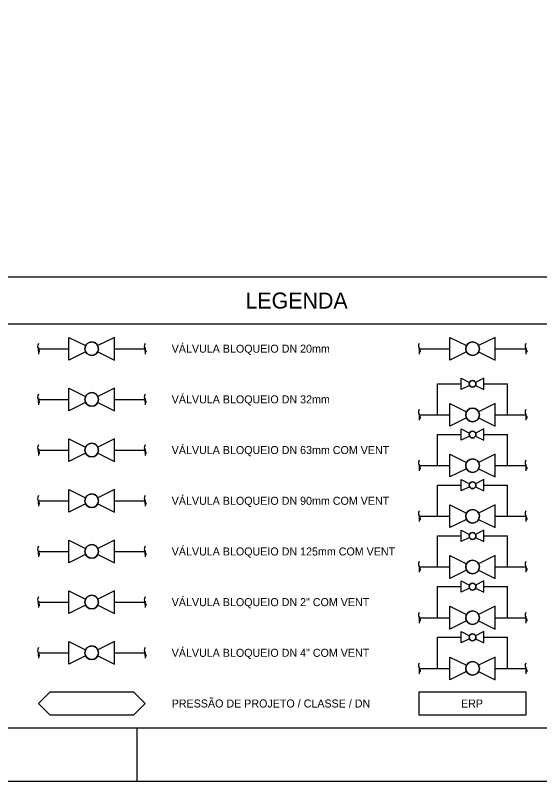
# Model space of a CAD drawing. Extents: x -1349 to -508, y 286 to 880.
# Drawn here: x -1031.4 to -933.1, y 285.8 to 429.5 of the extents above; entities that cross this region are included whole.
import ezdxf

# ---------------------------------------------------------------- set-up
doc = ezdxf.new("R2010")
doc.units = 0
for name, color, linetype in [('FORMATO', 7, 'Continuous'), ('LEGENDA', 7, 'Continuous'), ('VALVULA_ACO_10', 7, 'Continuous'), ('VALVULA_ACO_12', 7, 'Continuous'), ('VALVULA_ACO_14', 7, 'Continuous'), ('VALVULA_ACO_16', 7, 'Continuous'), ('VALVULA_ACO_18', 7, 'Continuous'), ('VALVULA_ACO_2', 7, 'Continuous'), ('VALVULA_ACO_4', 7, 'Continuous'), ('VALVULA_ACO_6', 7, 'Continuous'), ('VALVULA_ACO_8', 7, 'Continuous'), ('VALVULA_PEAD_125', 7, 'Continuous'), ('VALVULA_PEAD_20', 7, 'Continuous'), ('VALVULA_PEAD_32', 7, 'Continuous'), ('VALVULA_PEAD_63', 7, 'Continuous'), ('VALVULA_PEAD_90', 7, 'Continuous')]:
    doc.layers.add(name, color=color, linetype=linetype)

msp = doc.modelspace()

# ---------------------------------------------------------------- linework, layer by layer
at = {"layer": 'FORMATO'}
msp.add_line((-518.04, 295.82), (-1344.05, 295.82), dxfattribs=at)
msp.add_lwpolyline([(-1349.05, 879.82), (-508.05, 879.82), (-508.05, 285.82), (-1349.05, 285.82)], close=True, dxfattribs=at)
for points in [[(-518.04, 380.36), (-1324.05, 380.36)], [(-1324.05, 371.63), (-693.05, 371.63)], [(-1008.55, 285.82), (-1008.55, 295.82)]]:
    msp.add_lwpolyline(points, dxfattribs=at)
at = {"layer": 'LEGENDA'}
for points in [[(-1024.9, 302.66), (-1009.27, 302.66), (-1007.08, 300.47), (-1007.08, 300.47), (-1009.27, 298.28), (-1024.9, 298.28), (-1027.08, 300.47), (-1027.08, 300.47)], [(-955.66, 302.66), (-935.66, 302.66), (-935.66, 298.28), (-955.66, 298.28)]]:
    msp.add_lwpolyline(points, close=True, dxfattribs=at)
at = {"layer": 'VALVULA_ACO_10'}
for points in [[(-952.23, 350.89), (-947.79, 350.89)], [(-952.23, 345.06), (-952.23, 350.89)], [(-946.23, 350.6), (-947.79, 349.82), (-947.79, 351.95), (-946.23, 351.17)], [(-945.09, 350.6), (-943.54, 349.82), (-943.54, 351.95), (-945.09, 351.17)], [(-943.54, 350.89), (-939.09, 350.89)], [(-939.09, 345.06), (-939.09, 350.89)], [(-946.8, 344.49), (-949.92, 342.94), (-949.92, 347.19), (-946.8, 345.63)], [(-944.52, 344.49), (-941.41, 342.94), (-941.41, 347.19), (-944.52, 345.63)], [(-955.66, 345.06), (-949.92, 345.06)], [(-941.41, 345.06), (-935.66, 345.06)]]:
    msp.add_lwpolyline(points, dxfattribs=at)
for centre, radius in [((-945.66, 350.89), 0.638), ((-945.66, 345.06), 1.28)]:
    msp.add_circle(centre, radius, dxfattribs=at)
for centre, radius, start, end in [((-945.66, 350.89), 0.638, 0, 180), ((-945.66, 350.89), 0.638, 180, 0), ((-945.66, 345.06), 1.28, 0, 180), ((-945.66, 345.06), 1.28, 180, 0)]:
    msp.add_arc(centre, radius, start, end, dxfattribs=at)
for points in [[(-955.66, 346.06), (-955.91, 345.56), (-955.66, 345.06), (-955.41, 344.56), (-955.66, 344.06), (-955.66, 346.06), (-955.66, 344.06)], [(-935.66, 346.06), (-935.91, 345.56), (-935.66, 345.06), (-935.41, 344.56), (-935.66, 344.06), (-935.66, 346.06), (-935.66, 344.06)]]:
    msp.add_open_spline(points, degree=3, dxfattribs=at)
at = {"layer": 'VALVULA_ACO_12'}
for points in [[(-946.23, 341.1), (-947.79, 340.32), (-947.79, 342.45), (-946.23, 341.67)], [(-945.09, 341.1), (-943.54, 340.32), (-943.54, 342.45), (-945.09, 341.67)], [(-952.23, 341.39), (-947.79, 341.39)], [(-952.23, 335.56), (-952.23, 341.39)], [(-943.54, 341.39), (-939.09, 341.39)], [(-939.09, 335.56), (-939.09, 341.39)], [(-946.8, 334.99), (-949.92, 333.44), (-949.92, 337.69), (-946.8, 336.13)], [(-944.52, 334.99), (-941.41, 333.44), (-941.41, 337.69), (-944.52, 336.13)], [(-955.66, 335.56), (-949.92, 335.56)], [(-941.41, 335.56), (-935.66, 335.56)]]:
    msp.add_lwpolyline(points, dxfattribs=at)
for centre, radius in [((-945.66, 341.39), 0.638), ((-945.66, 335.56), 1.28)]:
    msp.add_circle(centre, radius, dxfattribs=at)
for centre, radius, start, end in [((-945.66, 341.39), 0.638, 0, 180), ((-945.66, 341.39), 0.638, 180, 0), ((-945.66, 335.56), 1.28, 0, 180), ((-945.66, 335.56), 1.28, 180, 0)]:
    msp.add_arc(centre, radius, start, end, dxfattribs=at)
for points in [[(-955.66, 336.56), (-955.91, 336.06), (-955.66, 335.56), (-955.41, 335.06), (-955.66, 334.56), (-955.66, 336.56), (-955.66, 334.56)], [(-935.66, 336.56), (-935.91, 336.06), (-935.66, 335.56), (-935.41, 335.06), (-935.66, 334.56), (-935.66, 336.56), (-935.66, 334.56)]]:
    msp.add_open_spline(points, degree=3, dxfattribs=at)
at = {"layer": 'VALVULA_ACO_14'}
for points in [[(-952.23, 331.88), (-947.79, 331.88)], [(-952.23, 326.06), (-952.23, 331.88)], [(-946.23, 331.6), (-947.79, 330.82), (-947.79, 332.95), (-946.23, 332.17)], [(-945.09, 331.6), (-943.54, 330.82), (-943.54, 332.95), (-945.09, 332.17)], [(-943.54, 331.88), (-939.09, 331.88)], [(-939.09, 326.06), (-939.09, 331.88)], [(-946.8, 325.49), (-949.92, 323.93), (-949.92, 328.19), (-946.8, 326.63)], [(-944.52, 325.49), (-941.41, 323.93), (-941.41, 328.19), (-944.52, 326.63)], [(-955.66, 326.06), (-949.92, 326.06)], [(-941.41, 326.06), (-935.66, 326.06)]]:
    msp.add_lwpolyline(points, dxfattribs=at)
for centre, radius in [((-945.66, 331.88), 0.638), ((-945.66, 326.06), 1.28)]:
    msp.add_circle(centre, radius, dxfattribs=at)
for centre, radius, start, end in [((-945.66, 331.88), 0.638, 0, 180), ((-945.66, 331.88), 0.638, 180, 0), ((-945.66, 326.06), 1.28, 0, 180), ((-945.66, 326.06), 1.28, 180, 0)]:
    msp.add_arc(centre, radius, start, end, dxfattribs=at)
for points in [[(-955.66, 327.06), (-955.91, 326.56), (-955.66, 326.06), (-955.41, 325.56), (-955.66, 325.06), (-955.66, 327.06), (-955.66, 325.06)], [(-935.66, 327.06), (-935.91, 326.56), (-935.66, 326.06), (-935.41, 325.56), (-935.66, 325.06), (-935.66, 327.06), (-935.66, 325.06)]]:
    msp.add_open_spline(points, degree=3, dxfattribs=at)
at = {"layer": 'VALVULA_ACO_16'}
for points in [[(-946.23, 322.1), (-947.79, 321.32), (-947.79, 323.45), (-946.23, 322.67)], [(-945.09, 322.1), (-943.54, 321.32), (-943.54, 323.45), (-945.09, 322.67)], [(-952.23, 322.38), (-947.79, 322.38)], [(-952.23, 316.56), (-952.23, 322.38)], [(-943.54, 322.38), (-939.09, 322.38)], [(-939.09, 316.56), (-939.09, 322.38)], [(-946.8, 315.99), (-949.92, 314.43), (-949.92, 318.69), (-946.8, 317.13)], [(-944.52, 315.99), (-941.41, 314.43), (-941.41, 318.69), (-944.52, 317.13)], [(-955.66, 316.56), (-949.92, 316.56)], [(-941.41, 316.56), (-935.66, 316.56)]]:
    msp.add_lwpolyline(points, dxfattribs=at)
for centre, radius in [((-945.66, 322.38), 0.638), ((-945.66, 316.56), 1.28)]:
    msp.add_circle(centre, radius, dxfattribs=at)
for centre, radius, start, end in [((-945.66, 322.38), 0.638, 0, 180), ((-945.66, 322.38), 0.638, 180, 0), ((-945.66, 316.56), 1.28, 0, 180), ((-945.66, 316.56), 1.28, 180, 0)]:
    msp.add_arc(centre, radius, start, end, dxfattribs=at)
for points in [[(-955.66, 317.56), (-955.91, 317.06), (-955.66, 316.56), (-955.41, 316.06), (-955.66, 315.56), (-955.66, 317.56), (-955.66, 315.56)], [(-935.66, 317.56), (-935.91, 317.06), (-935.66, 316.56), (-935.41, 316.06), (-935.66, 315.56), (-935.66, 317.56), (-935.66, 315.56)]]:
    msp.add_open_spline(points, degree=3, dxfattribs=at)
at = {"layer": 'VALVULA_ACO_18'}
for points in [[(-946.23, 312.6), (-947.79, 311.82), (-947.79, 313.94), (-946.23, 313.17)], [(-945.09, 312.6), (-943.54, 311.82), (-943.54, 313.94), (-945.09, 313.17)], [(-952.23, 312.88), (-947.79, 312.88)], [(-952.23, 307.06), (-952.23, 312.88)], [(-943.54, 312.88), (-939.09, 312.88)], [(-939.09, 307.06), (-939.09, 312.88)], [(-946.8, 306.49), (-949.92, 304.93), (-949.92, 309.18), (-946.8, 307.63)], [(-944.52, 306.49), (-941.41, 304.93), (-941.41, 309.18), (-944.52, 307.63)], [(-955.66, 307.06), (-949.92, 307.06)], [(-941.41, 307.06), (-935.66, 307.06)]]:
    msp.add_lwpolyline(points, dxfattribs=at)
for centre, radius in [((-945.66, 312.88), 0.638), ((-945.66, 307.06), 1.28)]:
    msp.add_circle(centre, radius, dxfattribs=at)
for centre, radius, start, end in [((-945.66, 312.88), 0.638, 0, 180), ((-945.66, 312.88), 0.638, 180, 0), ((-945.66, 307.06), 1.28, 0, 180), ((-945.66, 307.06), 1.28, 180, 0)]:
    msp.add_arc(centre, radius, start, end, dxfattribs=at)
for points in [[(-955.66, 308.06), (-955.91, 307.56), (-955.66, 307.06), (-955.41, 306.56), (-955.66, 306.06), (-955.66, 308.06), (-955.66, 306.06)], [(-935.66, 308.06), (-935.91, 307.56), (-935.66, 307.06), (-935.41, 306.56), (-935.66, 306.06), (-935.66, 308.06), (-935.66, 306.06)]]:
    msp.add_open_spline(points, degree=3, dxfattribs=at)
at = {"layer": 'VALVULA_ACO_2'}
for points in [[(-1018.22, 318.9), (-1021.34, 317.34), (-1021.34, 321.6), (-1018.22, 320.04)], [(-1015.94, 318.9), (-1012.83, 317.34), (-1012.83, 321.6), (-1015.94, 320.04)], [(-1027.08, 319.47), (-1021.34, 319.47)], [(-1012.83, 319.47), (-1007.08, 319.47)]]:
    msp.add_lwpolyline(points, dxfattribs=at)
msp.add_circle((-1017.08, 319.47), 1.28, dxfattribs=at)
for start, end in [(0, 180), (180, 0)]:
    msp.add_arc((-1017.08, 319.47), 1.28, start, end, dxfattribs=at)
for points in [[(-1027.08, 320.47), (-1027.33, 319.97), (-1027.08, 319.47), (-1026.83, 318.97), (-1027.08, 318.47), (-1027.08, 320.47), (-1027.08, 318.47)], [(-1007.08, 320.47), (-1007.33, 319.97), (-1007.08, 319.47), (-1006.83, 318.97), (-1007.08, 318.47), (-1007.08, 320.47), (-1007.08, 318.47)]]:
    msp.add_open_spline(points, degree=3, dxfattribs=at)
at = {"layer": 'VALVULA_ACO_4'}
for points in [[(-1018.22, 309.4), (-1021.34, 307.84), (-1021.34, 312.1), (-1018.22, 310.54)], [(-1015.94, 309.4), (-1012.83, 307.84), (-1012.83, 312.1), (-1015.94, 310.54)], [(-1027.08, 309.97), (-1021.34, 309.97)], [(-1012.83, 309.97), (-1007.08, 309.97)]]:
    msp.add_lwpolyline(points, dxfattribs=at)
msp.add_circle((-1017.08, 309.97), 1.28, dxfattribs=at)
for start, end in [(0, 180), (180, 0)]:
    msp.add_arc((-1017.08, 309.97), 1.28, start, end, dxfattribs=at)
for points in [[(-1027.08, 310.97), (-1027.33, 310.47), (-1027.08, 309.97), (-1026.83, 309.47), (-1027.08, 308.97), (-1027.08, 310.97), (-1027.08, 308.97)], [(-1007.08, 310.97), (-1007.33, 310.47), (-1007.08, 309.97), (-1006.83, 309.47), (-1007.08, 308.97), (-1007.08, 310.97), (-1007.08, 308.97)]]:
    msp.add_open_spline(points, degree=3, dxfattribs=at)
at = {"layer": 'VALVULA_ACO_6'}
for points in [[(-946.8, 366.41), (-949.92, 364.85), (-949.92, 369.11), (-946.8, 367.55)], [(-944.52, 366.41), (-941.41, 364.85), (-941.41, 369.11), (-944.52, 367.55)], [(-955.66, 366.98), (-949.92, 366.98)], [(-941.41, 366.98), (-935.66, 366.98)]]:
    msp.add_lwpolyline(points, dxfattribs=at)
msp.add_circle((-945.66, 366.98), 1.28, dxfattribs=at)
for start, end in [(0, 180), (180, 0)]:
    msp.add_arc((-945.66, 366.98), 1.28, start, end, dxfattribs=at)
for points in [[(-955.66, 367.98), (-955.91, 367.48), (-955.66, 366.98), (-955.41, 366.48), (-955.66, 365.98), (-955.66, 367.98), (-955.66, 365.98)], [(-935.66, 367.98), (-935.91, 367.48), (-935.66, 366.98), (-935.41, 366.48), (-935.66, 365.98), (-935.66, 367.98), (-935.66, 365.98)]]:
    msp.add_open_spline(points, degree=3, dxfattribs=at)
at = {"layer": 'VALVULA_ACO_8'}
for points in [[(-946.23, 360.1), (-947.79, 359.33), (-947.79, 361.45), (-946.23, 360.67)], [(-945.09, 360.1), (-943.54, 359.33), (-943.54, 361.45), (-945.09, 360.67)], [(-952.23, 360.39), (-947.79, 360.39)], [(-952.23, 354.57), (-952.23, 360.39)], [(-943.54, 360.39), (-939.09, 360.39)], [(-939.09, 354.57), (-939.09, 360.39)], [(-946.8, 354), (-949.92, 352.44), (-949.92, 356.69), (-946.8, 355.14)], [(-944.52, 354), (-941.41, 352.44), (-941.41, 356.69), (-944.52, 355.14)], [(-955.66, 354.57), (-949.92, 354.57)], [(-941.41, 354.57), (-935.66, 354.57)]]:
    msp.add_lwpolyline(points, dxfattribs=at)
for centre, radius in [((-945.66, 360.39), 0.638), ((-945.66, 354.57), 1.28)]:
    msp.add_circle(centre, radius, dxfattribs=at)
for centre, radius, start, end in [((-945.66, 360.39), 0.638, 0, 180), ((-945.66, 360.39), 0.638, 180, 0), ((-945.66, 354.57), 1.28, 0, 180), ((-945.66, 354.57), 1.28, 180, 0)]:
    msp.add_arc(centre, radius, start, end, dxfattribs=at)
for points in [[(-955.66, 355.57), (-955.91, 355.07), (-955.66, 354.57), (-955.41, 354.07), (-955.66, 353.57), (-955.66, 355.57), (-955.66, 353.57)], [(-935.66, 355.57), (-935.91, 355.07), (-935.66, 354.57), (-935.41, 354.07), (-935.66, 353.57), (-935.66, 355.57), (-935.66, 353.57)]]:
    msp.add_open_spline(points, degree=3, dxfattribs=at)
at = {"layer": 'VALVULA_PEAD_125'}
for points in [[(-1018.22, 328.4), (-1021.34, 326.85), (-1021.34, 331.1), (-1018.22, 329.54)], [(-1015.94, 328.4), (-1012.83, 326.85), (-1012.83, 331.1), (-1015.94, 329.54)], [(-1027.08, 328.97), (-1021.34, 328.97)], [(-1012.83, 328.97), (-1007.08, 328.97)]]:
    msp.add_lwpolyline(points, dxfattribs=at)
msp.add_circle((-1017.08, 328.97), 1.28, dxfattribs=at)
for start, end in [(0, 180), (180, 0)]:
    msp.add_arc((-1017.08, 328.97), 1.28, start, end, dxfattribs=at)
for points in [[(-1027.08, 329.97), (-1027.33, 329.47), (-1027.08, 328.97), (-1026.83, 328.47), (-1027.08, 327.97), (-1027.08, 329.97), (-1027.08, 327.97)], [(-1007.08, 329.97), (-1007.33, 329.47), (-1007.08, 328.97), (-1006.83, 328.47), (-1007.08, 327.97), (-1007.08, 329.97), (-1007.08, 327.97)]]:
    msp.add_open_spline(points, degree=3, dxfattribs=at)
at = {"layer": 'VALVULA_PEAD_20'}
for points in [[(-1018.22, 366.41), (-1021.34, 364.85), (-1021.34, 369.11), (-1018.22, 367.55)], [(-1015.94, 366.41), (-1012.83, 364.85), (-1012.83, 369.11), (-1015.94, 367.55)], [(-1027.08, 366.98), (-1021.34, 366.98)], [(-1012.83, 366.98), (-1007.08, 366.98)]]:
    msp.add_lwpolyline(points, dxfattribs=at)
msp.add_circle((-1017.08, 366.98), 1.28, dxfattribs=at)
for start, end in [(0, 180), (180, 0)]:
    msp.add_arc((-1017.08, 366.98), 1.28, start, end, dxfattribs=at)
for points in [[(-1027.08, 367.98), (-1027.33, 367.48), (-1027.08, 366.98), (-1026.83, 366.48), (-1027.08, 365.98), (-1027.08, 367.98), (-1027.08, 365.98)], [(-1007.08, 367.98), (-1007.33, 367.48), (-1007.08, 366.98), (-1006.83, 366.48), (-1007.08, 365.98), (-1007.08, 367.98), (-1007.08, 365.98)]]:
    msp.add_open_spline(points, degree=3, dxfattribs=at)
at = {"layer": 'VALVULA_PEAD_32'}
for points in [[(-1018.22, 356.91), (-1021.34, 355.35), (-1021.34, 359.6), (-1018.22, 358.05)], [(-1015.94, 356.91), (-1012.83, 355.35), (-1012.83, 359.6), (-1015.94, 358.05)], [(-1027.08, 357.48), (-1021.34, 357.48)], [(-1012.83, 357.48), (-1007.08, 357.48)]]:
    msp.add_lwpolyline(points, dxfattribs=at)
msp.add_circle((-1017.08, 357.48), 1.28, dxfattribs=at)
for start, end in [(0, 180), (180, 0)]:
    msp.add_arc((-1017.08, 357.48), 1.28, start, end, dxfattribs=at)
for points in [[(-1027.08, 358.48), (-1027.33, 357.98), (-1027.08, 357.48), (-1026.83, 356.98), (-1027.08, 356.48), (-1027.08, 358.48), (-1027.08, 356.48)], [(-1007.08, 358.48), (-1007.33, 357.98), (-1007.08, 357.48), (-1006.83, 356.98), (-1007.08, 356.48), (-1007.08, 358.48), (-1007.08, 356.48)]]:
    msp.add_open_spline(points, degree=3, dxfattribs=at)
at = {"layer": 'VALVULA_PEAD_63'}
for points in [[(-1018.22, 347.41), (-1021.34, 345.85), (-1021.34, 350.1), (-1018.22, 348.55)], [(-1015.94, 347.41), (-1012.83, 345.85), (-1012.83, 350.1), (-1015.94, 348.55)], [(-1027.08, 347.98), (-1021.34, 347.98)], [(-1012.83, 347.98), (-1007.08, 347.98)]]:
    msp.add_lwpolyline(points, dxfattribs=at)
msp.add_circle((-1017.08, 347.98), 1.28, dxfattribs=at)
for start, end in [(0, 180), (180, 0)]:
    msp.add_arc((-1017.08, 347.98), 1.28, start, end, dxfattribs=at)
for points in [[(-1027.08, 348.98), (-1027.33, 348.48), (-1027.08, 347.98), (-1026.83, 347.48), (-1027.08, 346.98), (-1027.08, 348.98), (-1027.08, 346.98)], [(-1007.08, 348.98), (-1007.33, 348.48), (-1007.08, 347.98), (-1006.83, 347.48), (-1007.08, 346.98), (-1007.08, 348.98), (-1007.08, 346.98)]]:
    msp.add_open_spline(points, degree=3, dxfattribs=at)
at = {"layer": 'VALVULA_PEAD_90'}
for points in [[(-1018.22, 337.9), (-1021.34, 336.35), (-1021.34, 340.6), (-1018.22, 339.04)], [(-1015.94, 337.9), (-1012.83, 336.35), (-1012.83, 340.6), (-1015.94, 339.04)], [(-1027.08, 338.47), (-1021.34, 338.47)], [(-1012.83, 338.47), (-1007.08, 338.47)]]:
    msp.add_lwpolyline(points, dxfattribs=at)
msp.add_circle((-1017.08, 338.47), 1.28, dxfattribs=at)
for start, end in [(0, 180), (180, 0)]:
    msp.add_arc((-1017.08, 338.47), 1.28, start, end, dxfattribs=at)
for points in [[(-1027.08, 339.47), (-1027.33, 338.97), (-1027.08, 338.47), (-1026.83, 337.97), (-1027.08, 337.47), (-1027.08, 339.47), (-1027.08, 337.47)], [(-1007.08, 339.47), (-1007.33, 338.97), (-1007.08, 338.47), (-1006.83, 337.97), (-1007.08, 337.47), (-1007.08, 339.47), (-1007.08, 337.47)]]:
    msp.add_open_spline(points, degree=3, dxfattribs=at)

# ---------------------------------------------------------------- texts
at = {"layer": 'FORMATO'}
msp.add_text('LEGENDA', height=3, rotation=360, dxfattribs=at).set_placement((-988.25, 374.5))
at = {"layer": 'LEGENDA'}
for s, p in [('VÁLVULA BLOQUEIO DN 20mm', (-1002.08, 366.23)), ('VÁLVULA BLOQUEIO DN 32mm', (-1002.08, 356.73)), ('VÁLVULA BLOQUEIO DN 63mm COM VENT', (-1002.08, 347.23)), ('VÁLVULA BLOQUEIO DN 90mm COM VENT', (-1002.08, 337.72)), ('VÁLVULA BLOQUEIO DN 125mm COM VENT', (-1002.08, 328.22)), ('VÁLVULA BLOQUEIO DN 2" COM VENT', (-1002.08, 318.72)), ('VÁLVULA BLOQUEIO DN 4" COM VENT', (-1002.08, 309.22)), ('PRESSÃO DE PROJETO / CLASSE / DN', (-1002.08, 299.72)), ('ERP', (-947.82, 299.72))]:
    msp.add_text(s, height=1.5, dxfattribs=at).set_placement(p)

doc.saveas('drawing.dxf')
